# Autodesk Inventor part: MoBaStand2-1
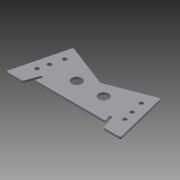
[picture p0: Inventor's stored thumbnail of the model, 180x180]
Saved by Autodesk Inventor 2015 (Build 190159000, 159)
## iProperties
Created: 2017-04
Part Number: MoBaStand2-1
Material: Generisch
Document SubType Name: Modeling
Designer: Andreas
Density: 1 g/cm^3
Appearance: Vorgabe
Author: Andreas
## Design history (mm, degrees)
sketch "Skizze1"
  geometry: L1 (2.562, 0)-(23.581, 0); L2 (32, 20)-(25.469, 1.339); L3 (32, 20)-(36, 20); L4 (36, 20)-(32.5, 10); L5 (85, 10)-(32.5, 10); L6 (19.452, 77.807)-(0.621, 2.485); L7 (22.11, 79.188)-(84.282, 55.276); L8 (147.89, 79.188)-(85.718, 55.276); L9 (85, 10)-(137.5, 10); L10 (134, 20)-(137.5, 10); L11 (138, 20)-(134, 20); L12 (138, 20)-(144.531, 1.339); L13 (167.438, 0)-(146.419, 0); L14 (150.548, 77.807)-(169.379, 2.485); A1 r 2 centre (21.392, 77.322) between (22.11, 79.188) and (19.452, 77.807); A2 r 2 centre (2.562, 2) between (0.621, 2.485) and (2.562, 0); A3 r 2 centre (23.581, 2) between (23.581, 0) and (25.469, 1.339); A4 r 2 centre (146.419, 2) between (144.531, 1.339) and (146.419, 0); A5 r 2 centre (167.438, 2) between (167.438, 0) and (169.379, 2.485); A6 r 2 centre (148.608, 77.322) between (150.548, 77.807) and (147.89, 79.188); A7 r 2 centre (85, 57.143) between (84.282, 55.276) and (85.718, 55.276); 5 further points
  constraints: 28 end point, 14 point on circle, 8 point on line, 8 tangent, 7 centre point, 3 horizontal, 2 equal radius, 1 coincident, 1 parallel
  dimensions: "d0" = 25 distance of point (0, 0) point (25, 0); "d5" = 2 radius of A1; "d6" = 52.5 distance of L5.start L4.end; "d7" = 10 distance between parallel lines of L1 L5; "d8" = 18.6607 vertical distance of L2.start L2.end; "d9" = 109.29 deg angle of L1 L2; "d13" = 75.32179 vertical distance of L6.start L6.end; "d14" = 75.9638 deg angle of L1 L6; "d15" = 62.89004 horizontal distance of L7.start point (85, 55); "d17" = 2 radius of A7; "d18" = 45 distance of point (85, 55) L5.start; "d19" = 52.5 distance of L5.start L9.end
extrude "Extrusion1" new body sketch "Skizze1" distance "d20" = 3; taper "d21" = 0 deg
sketch "Skizze2"
  geometry: L1 (25.469, 1.339)-(32, 20) reference; L2 (32, 20)-(36, 20) reference; L3 (36, 20)-(32.5, 10) reference; L4 (32.5, 10)-(137.5, 10) reference; L5 (137.5, 10)-(134, 20) reference; L6 (134, 20)-(138, 20) reference; L7 (138, 20)-(144.531, 1.339) reference; L8 (146.419, 0)-(167.438, 0) reference; L9 (169.379, 2.485)-(150.548, 77.807) reference; L10 (147.89, 79.188)-(85.718, 55.276) reference; L11 (84.282, 55.276)-(22.11, 79.188) reference; L12 (19.452, 77.807)-(0.621, 2.485) reference; L13 (2.562, 0)-(23.581, 0) reference; L14 (146.419, 0)-(167.438, 0) reference; L15 (167.438, 0)-(167.438, 0); L16 (156.929, 0)-(139.457, 68.049); L17 (156.929, 0)-(227.185, 0); C1 r 7.5 at (105, 40); C2 r 3 at (141.734, 59.181); C3 r 3 at (146.404, 40.991); C4 r 3 at (150.173, 26.31); C5 r 7.5 at (65, 40); C6 r 3 at (23.596, 40.991); C7 r 3 at (28.266, 59.181); C8 r 3 at (19.827, 26.31); A1 r 2 centre (146.419, 2) between (144.531, 1.339) and (146.419, 0) reference; A2 r 2 centre (167.438, 2) between (167.438, 0) and (169.379, 2.485) reference; A3 r 2 centre (148.608, 77.322) between (150.548, 77.807) and (147.89, 79.188) reference; A4 r 2 centre (85, 57.143) between (84.282, 55.276) and (85.718, 55.276) reference; A5 r 2 centre (21.392, 77.322) between (22.11, 79.188) and (19.452, 77.807) reference; A6 r 2 centre (2.562, 2) between (0.621, 2.485) and (2.562, 0) reference; A7 r 2 centre (23.581, 2) between (23.581, 0) and (25.469, 1.339) reference; A8 r 2 centre (167.438, 2) between (167.438, 0) and (169.379, 2.485) reference; 3 further points
  constraints: 8 centre point, 6 end point, 5 point on line, 1 coincident, 1 equal length, 1 horizontal, 1 midpoint, 1 tangent
  dimensions: "d22" = 20 distance of point (105, 40) point (85, 40); "d25" = 15 diameter of C1; "d28" = 75.9638 deg angle of L8 L9 (derived); "d29" = 104.036 deg angle of L15 L9; "d30" = 104.4 deg angle of L17 L16; "d31" = 6 diameter of C2; "d32" = 6 diameter of C3; "d33" = 6 diameter of C4
extrude "Extrusion2" cut sketch "Skizze2" distance "d34" = 3; taper "d35" = 0 deg
node "Volumenkörper1"
node "Projizierte Kontur1"
